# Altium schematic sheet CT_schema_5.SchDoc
size 314 x 170 mm
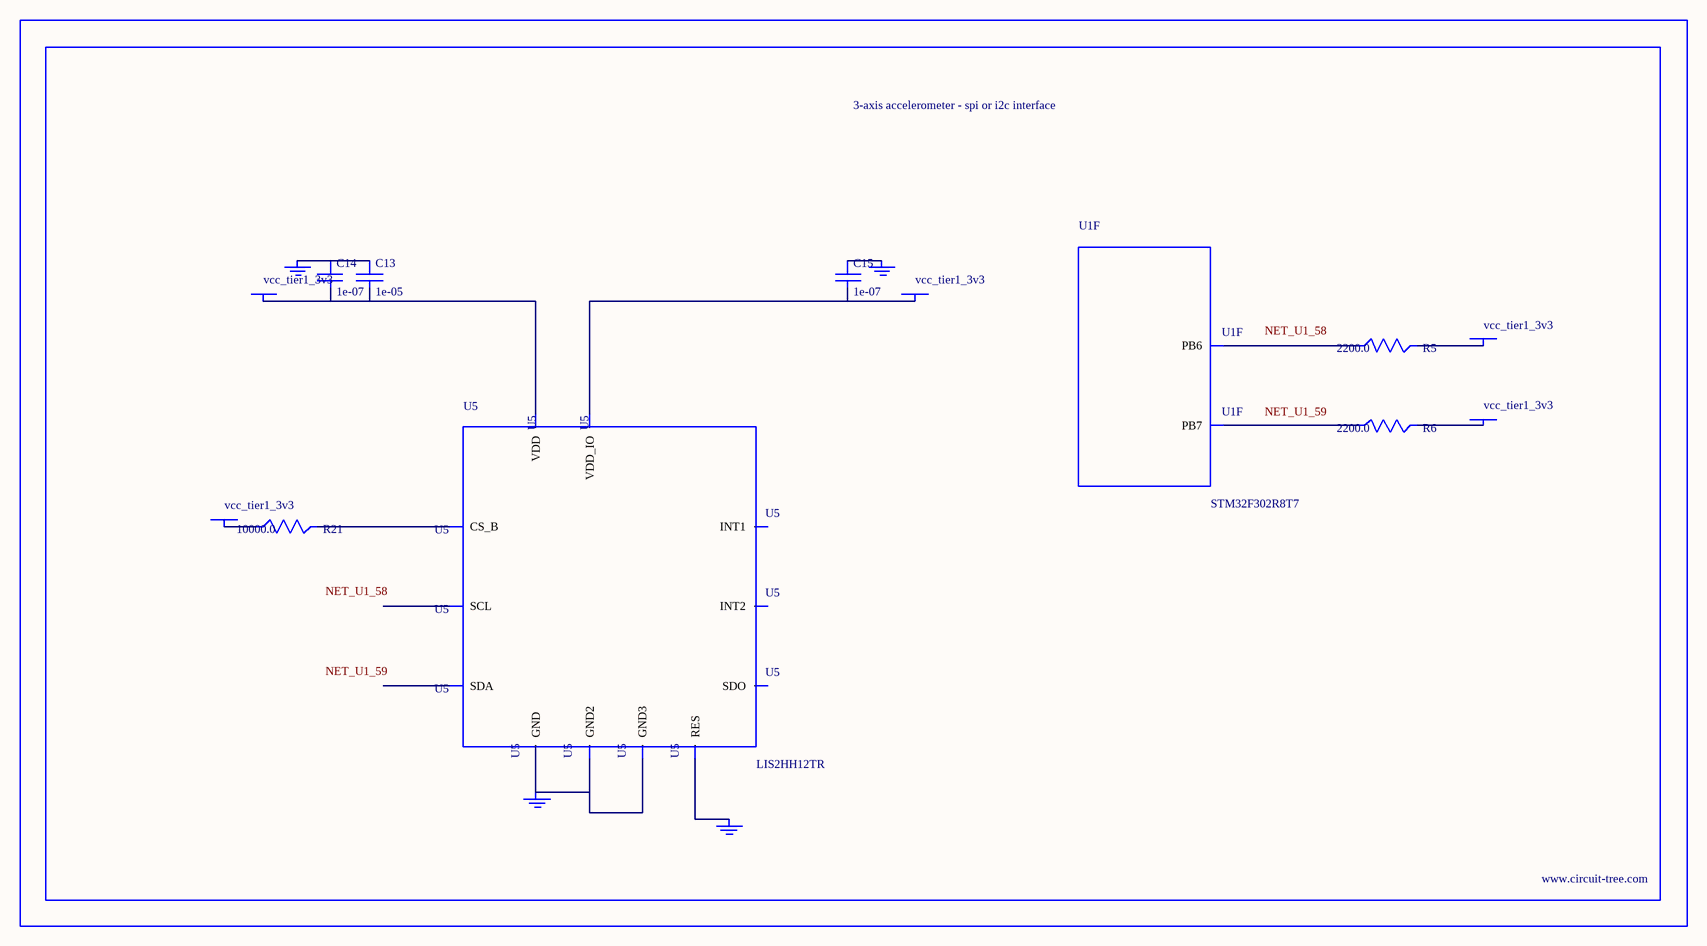
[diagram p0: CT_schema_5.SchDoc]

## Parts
BORDER4  (no value)
C13  1e-05  [C0805]
C14  1e-07  [C0402]
C15  1e-07  [C0402]
GND_INSTANCE_4_0  (no value)
GND_INSTANCE_4_1  (no value)
GND_INSTANCE_4_2  (no value)
GND_INSTANCE_4_3  (no value)
POWER_INSTANCE_4_0  vcc_tier1_3v3
POWER_INSTANCE_4_1  vcc_tier1_3v3
POWER_INSTANCE_4_2  vcc_tier1_3v3
POWER_INSTANCE_4_3  vcc_tier1_3v3
POWER_INSTANCE_4_4  vcc_tier1_3v3
R5  2200.0  [R0603]
R6  2200.0  [R0603]
R21  10000.0  [R0603]
U1  STM32F302R8T7  [LQFP64]  (part F of 8)
U5  LIS2HH12TR  [LGA-12]

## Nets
NetC13_1: C13.1 C14.1 GND_INSTANCE_4_1.0(GND)
NetC13_2: C13.2 C14.2 POWER_INSTANCE_4_1.0(PWR) U5.9(VDD)
NetC15_1: C15.1 GND_INSTANCE_4_2.0(GND)
NetC15_2: C15.2 POWER_INSTANCE_4_2.0(PWR) U5.10(VDD_IO)
NetGND_INSTANCE_4_0_0: GND_INSTANCE_4_0.0(GND) U5.5(RES)
NetGND_INSTANCE_4_3_0: GND_INSTANCE_4_3.0(GND) U5.6(GND) U5.7(GND2) U5.8(GND3)
NetPOWER_INSTANCE_4_0_0: POWER_INSTANCE_4_0.0(PWR) R21.1
NetPOWER_INSTANCE_4_3_0: POWER_INSTANCE_4_3.0(PWR) R5.2
NetPOWER_INSTANCE_4_4_0: POWER_INSTANCE_4_4.0(PWR) R6.2
NetR5_1: R5.1 U1.58(PB6)
NetR6_1: R6.1 U1.59(PB7)
NetR21_2: R21.2 U5.2(CS_B)

Not connected (* = marked no-connect by the designer): U5 1(SCL) 3(SDO) 4(SDA) 11(INT2) 12(INT1)

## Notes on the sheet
- Labels drawn without touching a wire or pin: NET_U1_58, NET_U1_59

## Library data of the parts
BORDER4 = BORDER_PAGE4
C13 = C0805C106K8RACTU
C14 C15 = C0402C104K3RACTU
GND_INSTANCE_4_0-GND_INSTANCE_4_3 = GND
POWER_INSTANCE_4_0-POWER_INSTANCE_4_4 = PWR
R5 R6 = RC0603JR-072K2L
R21 = RC0603JR-0710KL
